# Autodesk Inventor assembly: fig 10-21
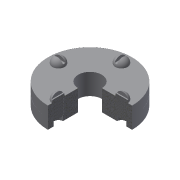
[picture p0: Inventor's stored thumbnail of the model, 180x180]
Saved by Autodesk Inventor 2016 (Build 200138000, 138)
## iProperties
Shininess: 64.0
Angle Display Precision: 2
Document Length Units: 11269
Document Angle Units: 11279
Document Time Units: 11290
Document Mass Units: 11283
Document Length Units Precision: 3
Document Angle Units Precision: 2
Created: 2002-02
Part Number: fig 10-21
Document SubType Name: Assembly
Designer: ***
Density: 0.0
Volumn: 0.0
Area: 0.0
PropertySet Name: Model Information
Control State: 0
Master: False
Checked Out: False
Author: ***
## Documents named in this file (3)
- D:\KAVITA\Autodesk Inventor_ 2016 Project_Kavita\Inventor_Part Files\Inventor_2016_Part\c10_Inv_2016\c10_inv_2016_prt\fig 10-21.iam
- D:\KAVITA\Autodesk Inventor_ 2016 Project_Kavita\Inventor_Part Files\Inventor_2016_Part\c10_Inv_2016\c10_inv_2016_prt\Screw.ipt
- D:\KAVITA\Autodesk Inventor_ 2016 Project_Kavita\Inventor_Part Files\Inventor_2016_Part\c10_Inv_2016\c10_inv_2016_prt\test.ipt
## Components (6 placed, 2 different names)
1. test:1 — Insert:1, Insert:2
2. test:2 — Insert:1
3. Screw:1 — Angle:1, Insert:2
4. Screw:11
5. Screw:12
6. Screw:13
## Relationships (3: Insert 2, Angle 1)
- Insert:1: test:1 ↔ test:2
- Angle:1: Screw:1
- Insert:2: test:1 ↔ Screw:1
